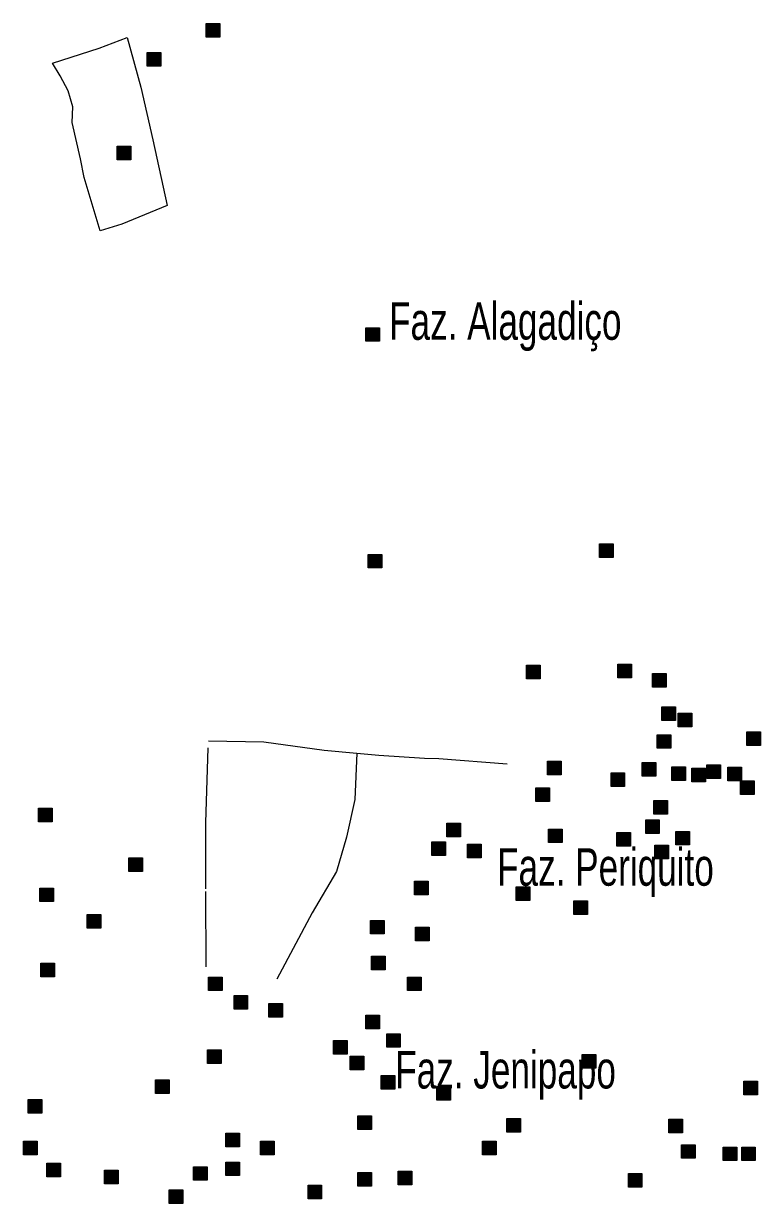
# Model space of a CAD drawing. Extents: x 445.4 to 500, y 8728.7 to 8784.
# Drawn here: x 485.38 to 488.52, y 8728.75 to 8733.78 of the extents above; entities that cross this region are included whole.
import ezdxf

# ---------------------------------------------------------------- set-up
doc = ezdxf.new("R2010")
doc.units = 0
doc.header["$LTSCALE"] = 0.064
doc.linetypes.add('DOT_DASHED', pattern=[7.7, 5, -1.2, 0.3, -1.2])
doc.layers.add('2', color=7, linetype='Continuous', lineweight=25)
doc.layers.add('22', color=7, linetype='DOT_DASHED', lineweight=13)
doc.layers.add('61', color=7, linetype='Continuous')

msp = doc.modelspace()

# ---------------------------------------------------------------- hatches: boundary and pattern name
at = {"layer": '2'}
for points in [[(486.1581, 8733.7784), (486.2161, 8733.7784), (486.2161, 8733.7204), (486.1581, 8733.7204)], [(485.9067, 8733.6551), (485.9647, 8733.6551), (485.9647, 8733.5971), (485.9067, 8733.5971)], [(485.7786, 8733.2556), (485.8366, 8733.2556), (485.8366, 8733.1976), (485.7786, 8733.1976)], [(486.8384, 8732.4814), (486.8964, 8732.4814), (486.8964, 8732.4234), (486.8384, 8732.4234)], [(487.8341, 8731.5591), (487.8921, 8731.5591), (487.8921, 8731.5011), (487.8341, 8731.5011)], [(486.8482, 8731.5147), (486.9062, 8731.5147), (486.9062, 8731.4567), (486.8482, 8731.4567)], [(487.9129, 8731.0462), (487.9709, 8731.0462), (487.9709, 8730.9882), (487.9129, 8730.9882)], [(487.5235, 8731.0413), (487.5815, 8731.0413), (487.5815, 8730.9833), (487.5235, 8730.9833)], [(488.0608, 8731.0068), (488.1188, 8731.0068), (488.1188, 8730.9488), (488.0608, 8730.9488)], [(488.1002, 8730.8638), (488.1582, 8730.8638), (488.1582, 8730.8058), (488.1002, 8730.8058)], [(488.1696, 8730.8372), (488.2276, 8730.8372), (488.2276, 8730.7792), (488.1696, 8730.7792)], [(488.0805, 8730.7454), (488.1385, 8730.7454), (488.1385, 8730.6874), (488.0805, 8730.6874)], [(488.4622, 8730.7571), (488.5202, 8730.7571), (488.5202, 8730.6991), (488.4622, 8730.6991)], [(487.6122, 8730.632), (487.6702, 8730.632), (487.6702, 8730.574), (487.6122, 8730.574)], [(488.0164, 8730.627), (488.0744, 8730.627), (488.0744, 8730.569), (488.0164, 8730.569)], [(488.143, 8730.6085), (488.201, 8730.6085), (488.201, 8730.5505), (488.143, 8730.5505)], [(488.2284, 8730.6024), (488.2864, 8730.6024), (488.2864, 8730.5444), (488.2284, 8730.5444)], [(488.2925, 8730.6172), (488.3505, 8730.6172), (488.3505, 8730.5592), (488.2925, 8730.5592)], [(488.3812, 8730.6073), (488.4392, 8730.6073), (488.4392, 8730.5493), (488.3812, 8730.5493)], [(487.8834, 8730.5826), (487.9414, 8730.5826), (487.9414, 8730.5246), (487.8834, 8730.5246)], [(488.4354, 8730.5481), (488.4934, 8730.5481), (488.4934, 8730.4901), (488.4354, 8730.4901)], [(487.563, 8730.5185), (487.621, 8730.5185), (487.621, 8730.4605), (487.563, 8730.4605)], [(488.0657, 8730.4643), (488.1237, 8730.4643), (488.1237, 8730.4063), (488.0657, 8730.4063)], [(485.4434, 8730.4318), (485.5014, 8730.4318), (485.5014, 8730.3738), (485.4434, 8730.3738)], [(487.1834, 8730.3677), (487.2414, 8730.3677), (487.2414, 8730.3097), (487.1834, 8730.3097)], [(487.6172, 8730.343), (487.6752, 8730.343), (487.6752, 8730.285), (487.6172, 8730.285)], [(488.0312, 8730.3824), (488.0892, 8730.3824), (488.0892, 8730.3244), (488.0312, 8730.3244)], [(487.908, 8730.3282), (487.966, 8730.3282), (487.966, 8730.2702), (487.908, 8730.2702)], [(488.1594, 8730.3331), (488.2174, 8730.3331), (488.2174, 8730.2751), (488.1594, 8730.2751)], [(487.1193, 8730.2887), (487.1773, 8730.2887), (487.1773, 8730.2307), (487.1193, 8730.2307)], [(487.2721, 8730.2789), (487.3301, 8730.2789), (487.3301, 8730.2209), (487.2721, 8730.2209)], [(488.0707, 8730.274), (488.1287, 8730.274), (488.1287, 8730.216), (488.0707, 8730.216)], [(485.8279, 8730.2197), (485.8859, 8730.2197), (485.8859, 8730.1617), (485.8279, 8730.1617)], [(485.4483, 8730.0915), (485.5063, 8730.0915), (485.5063, 8730.0335), (485.4483, 8730.0335)], [(487.0454, 8730.1211), (487.1034, 8730.1211), (487.1034, 8730.0631), (487.0454, 8730.0631)], [(487.4792, 8730.0964), (487.5372, 8730.0964), (487.5372, 8730.0384), (487.4792, 8730.0384)], [(487.7256, 8730.0372), (487.7836, 8730.0372), (487.7836, 8729.9792), (487.7256, 8729.9792)], [(485.6504, 8729.978), (485.7084, 8729.978), (485.7084, 8729.92), (485.6504, 8729.92)], [(486.8581, 8729.9534), (486.9161, 8729.9534), (486.9161, 8729.8954), (486.8581, 8729.8954)], [(487.0503, 8729.9238), (487.1083, 8729.9238), (487.1083, 8729.8658), (487.0503, 8729.8658)], [(486.863, 8729.8005), (486.921, 8729.8005), (486.921, 8729.7425), (486.863, 8729.7425)], [(485.4532, 8729.7709), (485.5112, 8729.7709), (485.5112, 8729.7129), (485.4532, 8729.7129)], [(486.168, 8729.7117), (486.226, 8729.7117), (486.226, 8729.6537), (486.168, 8729.6537)], [(487.0158, 8729.7117), (487.0738, 8729.7117), (487.0738, 8729.6537), (487.0158, 8729.6537)], [(486.2764, 8729.6328), (486.3344, 8729.6328), (486.3344, 8729.5748), (486.2764, 8729.5748)], [(486.4243, 8729.5983), (486.4823, 8729.5983), (486.4823, 8729.5403), (486.4243, 8729.5403)], [(486.8384, 8729.549), (486.8964, 8729.549), (486.8964, 8729.491), (486.8384, 8729.491)], [(486.7003, 8729.4405), (486.7583, 8729.4405), (486.7583, 8729.3825), (486.7003, 8729.3825)], [(486.9271, 8729.4701), (486.9851, 8729.4701), (486.9851, 8729.4121), (486.9271, 8729.4121)], [(486.163, 8729.401), (486.221, 8729.401), (486.221, 8729.343), (486.163, 8729.343)], [(486.772, 8729.3737), (486.83, 8729.3737), (486.83, 8729.3157), (486.772, 8729.3157)], [(487.7601, 8729.3813), (487.8181, 8729.3813), (487.8181, 8729.3233), (487.7601, 8729.3233)], [(486.9032, 8729.2918), (486.9612, 8729.2918), (486.9612, 8729.2338), (486.9032, 8729.2338)], [(485.9412, 8729.2728), (485.9992, 8729.2728), (485.9992, 8729.2148), (485.9412, 8729.2148)], [(487.1409, 8729.2444), (487.1989, 8729.2444), (487.1989, 8729.1864), (487.1409, 8729.1864)], [(488.4502, 8729.2679), (488.5082, 8729.2679), (488.5082, 8729.2099), (488.4502, 8729.2099)], [(485.399, 8729.189), (485.457, 8729.189), (485.457, 8729.131), (485.399, 8729.131)], [(486.8039, 8729.1199), (486.8619, 8729.1199), (486.8619, 8729.0619), (486.8039, 8729.0619)], [(487.439, 8729.108), (487.497, 8729.108), (487.497, 8729.05), (487.439, 8729.05)], [(488.1298, 8729.1051), (488.1878, 8729.1051), (488.1878, 8729.0471), (488.1298, 8729.0471)], [(486.2419, 8729.046), (486.2999, 8729.046), (486.2999, 8728.988), (486.2419, 8728.988)], [(485.3793, 8729.0114), (485.4373, 8729.0114), (485.4373, 8728.9534), (485.3793, 8728.9534)], [(486.3898, 8729.0114), (486.4478, 8729.0114), (486.4478, 8728.9534), (486.3898, 8728.9534)], [(487.3362, 8729.0114), (487.3942, 8729.0114), (487.3942, 8728.9534), (487.3362, 8728.9534)], [(488.184, 8728.9966), (488.242, 8728.9966), (488.242, 8728.9386), (488.184, 8728.9386)], [(488.3615, 8728.9868), (488.4195, 8728.9868), (488.4195, 8728.9288), (488.3615, 8728.9288)], [(488.4404, 8728.9868), (488.4984, 8728.9868), (488.4984, 8728.9288), (488.4404, 8728.9288)], [(485.4779, 8728.9177), (485.5359, 8728.9177), (485.5359, 8728.8597), (485.4779, 8728.8597)], [(485.7243, 8728.8881), (485.7823, 8728.8881), (485.7823, 8728.8301), (485.7243, 8728.8301)], [(486.1039, 8728.9029), (486.1619, 8728.9029), (486.1619, 8728.8449), (486.1039, 8728.8449)], [(486.2419, 8728.9227), (486.2999, 8728.9227), (486.2999, 8728.8647), (486.2419, 8728.8647)], [(486.9764, 8728.8832), (487.0344, 8728.8832), (487.0344, 8728.8252), (486.9764, 8728.8252)], [(486.8039, 8728.8783), (486.8619, 8728.8783), (486.8619, 8728.8203), (486.8039, 8728.8203)], [(487.9573, 8728.8733), (488.0153, 8728.8733), (488.0153, 8728.8153), (487.9573, 8728.8153)], [(486.0004, 8728.8043), (486.0584, 8728.8043), (486.0584, 8728.7463), (486.0004, 8728.7463)], [(486.5919, 8728.824), (486.6499, 8728.824), (486.6499, 8728.766), (486.5919, 8728.766)]]:
    msp.add_hatch(color=256, dxfattribs=at).paths.add_polyline_path(points)

# ---------------------------------------------------------------- linework, layer by layer
for points in [[(486.1581, 8733.7784), (486.2161, 8733.7784), (486.2161, 8733.7204), (486.1581, 8733.7204)], [(485.9067, 8733.6551), (485.9647, 8733.6551), (485.9647, 8733.5971), (485.9067, 8733.5971)], [(485.7786, 8733.2556), (485.8366, 8733.2556), (485.8366, 8733.1976), (485.7786, 8733.1976)], [(486.8384, 8732.4814), (486.8964, 8732.4814), (486.8964, 8732.4234), (486.8384, 8732.4234)], [(487.8341, 8731.5591), (487.8921, 8731.5591), (487.8921, 8731.5011), (487.8341, 8731.5011)], [(486.8482, 8731.5147), (486.9062, 8731.5147), (486.9062, 8731.4567), (486.8482, 8731.4567)], [(487.9129, 8731.0462), (487.9709, 8731.0462), (487.9709, 8730.9882), (487.9129, 8730.9882)], [(487.5235, 8731.0413), (487.5815, 8731.0413), (487.5815, 8730.9833), (487.5235, 8730.9833)], [(488.0608, 8731.0068), (488.1188, 8731.0068), (488.1188, 8730.9488), (488.0608, 8730.9488)], [(488.1002, 8730.8638), (488.1582, 8730.8638), (488.1582, 8730.8058), (488.1002, 8730.8058)], [(488.1696, 8730.8372), (488.2276, 8730.8372), (488.2276, 8730.7792), (488.1696, 8730.7792)], [(488.0805, 8730.7454), (488.1385, 8730.7454), (488.1385, 8730.6874), (488.0805, 8730.6874)], [(488.4622, 8730.7571), (488.5202, 8730.7571), (488.5202, 8730.6991), (488.4622, 8730.6991)], [(487.6122, 8730.632), (487.6702, 8730.632), (487.6702, 8730.574), (487.6122, 8730.574)], [(488.0164, 8730.627), (488.0744, 8730.627), (488.0744, 8730.569), (488.0164, 8730.569)], [(488.143, 8730.6085), (488.201, 8730.6085), (488.201, 8730.5505), (488.143, 8730.5505)], [(488.2284, 8730.6024), (488.2864, 8730.6024), (488.2864, 8730.5444), (488.2284, 8730.5444)], [(488.2925, 8730.6172), (488.3505, 8730.6172), (488.3505, 8730.5592), (488.2925, 8730.5592)], [(488.3812, 8730.6073), (488.4392, 8730.6073), (488.4392, 8730.5493), (488.3812, 8730.5493)], [(487.8834, 8730.5826), (487.9414, 8730.5826), (487.9414, 8730.5246), (487.8834, 8730.5246)], [(488.4354, 8730.5481), (488.4934, 8730.5481), (488.4934, 8730.4901), (488.4354, 8730.4901)], [(487.563, 8730.5185), (487.621, 8730.5185), (487.621, 8730.4605), (487.563, 8730.4605)], [(488.0657, 8730.4643), (488.1237, 8730.4643), (488.1237, 8730.4063), (488.0657, 8730.4063)], [(485.4434, 8730.4318), (485.5014, 8730.4318), (485.5014, 8730.3738), (485.4434, 8730.3738)], [(487.1834, 8730.3677), (487.2414, 8730.3677), (487.2414, 8730.3097), (487.1834, 8730.3097)], [(487.6172, 8730.343), (487.6752, 8730.343), (487.6752, 8730.285), (487.6172, 8730.285)], [(488.0312, 8730.3824), (488.0892, 8730.3824), (488.0892, 8730.3244), (488.0312, 8730.3244)], [(487.908, 8730.3282), (487.966, 8730.3282), (487.966, 8730.2702), (487.908, 8730.2702)], [(488.1594, 8730.3331), (488.2174, 8730.3331), (488.2174, 8730.2751), (488.1594, 8730.2751)], [(487.1193, 8730.2887), (487.1773, 8730.2887), (487.1773, 8730.2307), (487.1193, 8730.2307)], [(487.2721, 8730.2789), (487.3301, 8730.2789), (487.3301, 8730.2209), (487.2721, 8730.2209)], [(488.0707, 8730.274), (488.1287, 8730.274), (488.1287, 8730.216), (488.0707, 8730.216)], [(485.8279, 8730.2197), (485.8859, 8730.2197), (485.8859, 8730.1617), (485.8279, 8730.1617)], [(485.4483, 8730.0915), (485.5063, 8730.0915), (485.5063, 8730.0335), (485.4483, 8730.0335)], [(487.0454, 8730.1211), (487.1034, 8730.1211), (487.1034, 8730.0631), (487.0454, 8730.0631)], [(487.4792, 8730.0964), (487.5372, 8730.0964), (487.5372, 8730.0384), (487.4792, 8730.0384)], [(487.7256, 8730.0372), (487.7836, 8730.0372), (487.7836, 8729.9792), (487.7256, 8729.9792)], [(485.6504, 8729.978), (485.7084, 8729.978), (485.7084, 8729.92), (485.6504, 8729.92)], [(486.8581, 8729.9534), (486.9161, 8729.9534), (486.9161, 8729.8954), (486.8581, 8729.8954)], [(487.0503, 8729.9238), (487.1083, 8729.9238), (487.1083, 8729.8658), (487.0503, 8729.8658)], [(486.863, 8729.8005), (486.921, 8729.8005), (486.921, 8729.7425), (486.863, 8729.7425)], [(485.4532, 8729.7709), (485.5112, 8729.7709), (485.5112, 8729.7129), (485.4532, 8729.7129)], [(486.168, 8729.7117), (486.226, 8729.7117), (486.226, 8729.6537), (486.168, 8729.6537)], [(487.0158, 8729.7117), (487.0738, 8729.7117), (487.0738, 8729.6537), (487.0158, 8729.6537)], [(486.2764, 8729.6328), (486.3344, 8729.6328), (486.3344, 8729.5748), (486.2764, 8729.5748)], [(486.4243, 8729.5983), (486.4823, 8729.5983), (486.4823, 8729.5403), (486.4243, 8729.5403)], [(486.8384, 8729.549), (486.8964, 8729.549), (486.8964, 8729.491), (486.8384, 8729.491)], [(486.7003, 8729.4405), (486.7583, 8729.4405), (486.7583, 8729.3825), (486.7003, 8729.3825)], [(486.9271, 8729.4701), (486.9851, 8729.4701), (486.9851, 8729.4121), (486.9271, 8729.4121)], [(486.163, 8729.401), (486.221, 8729.401), (486.221, 8729.343), (486.163, 8729.343)], [(486.772, 8729.3737), (486.83, 8729.3737), (486.83, 8729.3157), (486.772, 8729.3157)], [(487.7601, 8729.3813), (487.8181, 8729.3813), (487.8181, 8729.3233), (487.7601, 8729.3233)], [(486.9032, 8729.2918), (486.9612, 8729.2918), (486.9612, 8729.2338), (486.9032, 8729.2338)], [(485.9412, 8729.2728), (485.9992, 8729.2728), (485.9992, 8729.2148), (485.9412, 8729.2148)], [(487.1409, 8729.2444), (487.1989, 8729.2444), (487.1989, 8729.1864), (487.1409, 8729.1864)], [(488.4502, 8729.2679), (488.5082, 8729.2679), (488.5082, 8729.2099), (488.4502, 8729.2099)], [(485.399, 8729.189), (485.457, 8729.189), (485.457, 8729.131), (485.399, 8729.131)], [(486.8039, 8729.1199), (486.8619, 8729.1199), (486.8619, 8729.0619), (486.8039, 8729.0619)], [(487.439, 8729.108), (487.497, 8729.108), (487.497, 8729.05), (487.439, 8729.05)], [(488.1298, 8729.1051), (488.1878, 8729.1051), (488.1878, 8729.0471), (488.1298, 8729.0471)], [(486.2419, 8729.046), (486.2999, 8729.046), (486.2999, 8728.988), (486.2419, 8728.988)], [(485.3793, 8729.0114), (485.4373, 8729.0114), (485.4373, 8728.9534), (485.3793, 8728.9534)], [(486.3898, 8729.0114), (486.4478, 8729.0114), (486.4478, 8728.9534), (486.3898, 8728.9534)], [(487.3362, 8729.0114), (487.3942, 8729.0114), (487.3942, 8728.9534), (487.3362, 8728.9534)], [(488.184, 8728.9966), (488.242, 8728.9966), (488.242, 8728.9386), (488.184, 8728.9386)], [(488.3615, 8728.9868), (488.4195, 8728.9868), (488.4195, 8728.9288), (488.3615, 8728.9288)], [(488.4404, 8728.9868), (488.4984, 8728.9868), (488.4984, 8728.9288), (488.4404, 8728.9288)], [(485.4779, 8728.9177), (485.5359, 8728.9177), (485.5359, 8728.8597), (485.4779, 8728.8597)], [(485.7243, 8728.8881), (485.7823, 8728.8881), (485.7823, 8728.8301), (485.7243, 8728.8301)], [(486.1039, 8728.9029), (486.1619, 8728.9029), (486.1619, 8728.8449), (486.1039, 8728.8449)], [(486.2419, 8728.9227), (486.2999, 8728.9227), (486.2999, 8728.8647), (486.2419, 8728.8647)], [(486.9764, 8728.8832), (487.0344, 8728.8832), (487.0344, 8728.8252), (486.9764, 8728.8252)], [(486.8039, 8728.8783), (486.8619, 8728.8783), (486.8619, 8728.8203), (486.8039, 8728.8203)], [(487.9573, 8728.8733), (488.0153, 8728.8733), (488.0153, 8728.8153), (487.9573, 8728.8153)], [(486.0004, 8728.8043), (486.0584, 8728.8043), (486.0584, 8728.7463), (486.0004, 8728.7463)], [(486.5919, 8728.824), (486.6499, 8728.824), (486.6499, 8728.766), (486.5919, 8728.766)]]:
    msp.add_lwpolyline(points, close=True, dxfattribs=at)
at = {"layer": '22'}
msp.add_lwpolyline([(485.5024, 8733.61), (485.7018, 8733.6743), (485.8208, 8733.7192), (485.8786, 8733.5073), (485.9301, 8733.2825), (485.9912, 8733.0031), (485.7983, 8732.9228), (485.705, 8732.8939), (485.6375, 8733.1219), (485.6214, 8733.2022), (485.586, 8733.3563), (485.5892, 8733.4238), (485.5699, 8733.4912), (485.5346, 8733.5554)], close=True, dxfattribs=at)
for points in [[(486.158, 8729.756), (486.1555, 8730.0887), (486.1555, 8730.3691), (486.1668, 8730.7188), (486.4027, 8730.7153), (486.661, 8730.6798), (486.7992, 8730.667)], [(486.7992, 8730.667), (486.7906, 8730.4684), (486.756, 8730.3087), (486.7128, 8730.1621), (486.6091, 8729.9852), (486.4432, 8729.6721)], [(486.7992, 8730.667), (486.8943, 8730.6582), (487.0887, 8730.6453), (487.1497, 8730.6435), (487.4403, 8730.6205)]]:
    msp.add_lwpolyline(points, dxfattribs=at)

# ---------------------------------------------------------------- texts
at = {"layer": '61', "width": 0.7}
for s, p in [('Faz. Alagadiço', (486.9373, 8732.4297)), ('Faz. Periquito', (487.3977, 8730.1013)), ('Faz. Jenipapo', (486.9635, 8729.2365))]:
    msp.add_text(s, height=0.16, dxfattribs=at).set_placement(p)

doc.saveas('drawing.dxf')
